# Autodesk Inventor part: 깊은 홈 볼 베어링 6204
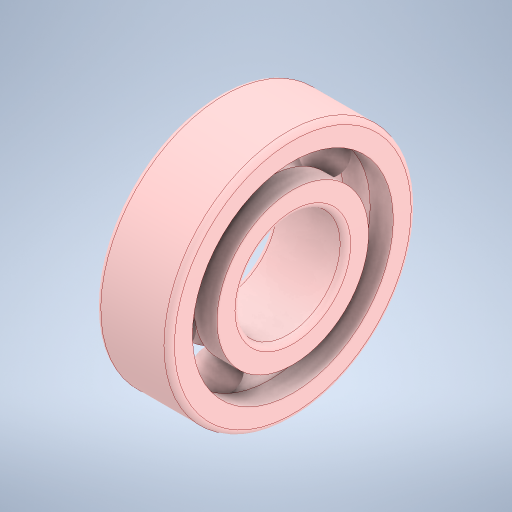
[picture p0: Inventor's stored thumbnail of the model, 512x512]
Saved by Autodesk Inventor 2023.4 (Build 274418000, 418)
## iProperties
Created: 2024-04
Part Number: 깊은 홈 볼 베어링 6204
Material: 강철, 연강
Description: 깊은 그루브 볼 베어링
Document SubType Name: Modeling
Designer: Edu03
Density: 7.85 g/cm^3
Appearance: 기본값
Author: jhkim
Sending System: Autodesk Inventor 2025
Preprocessor: ST-DEVELOPER v20
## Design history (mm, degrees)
feature "Solid1"
feature "Solid1:1"
feature "Solid1:2"
feature "Solid1:3"
feature "Solid1:4"
feature "Solid1:5"
feature "Solid1:6"
feature "Solid1:7"
feature "Solid1:8"
node "솔리드1"
node "솔리드2"
node "솔리드3"
node "솔리드4"
node "솔리드5"
node "솔리드6"
node "솔리드7"
node "솔리드8"
node "솔리드9"
